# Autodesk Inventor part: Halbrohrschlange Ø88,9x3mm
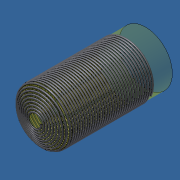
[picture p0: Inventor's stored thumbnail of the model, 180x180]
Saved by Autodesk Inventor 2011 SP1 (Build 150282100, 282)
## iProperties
Created: 2012-07
Part Number: Halbrohrschlange Ø88,9x3mm
Material: 1.4301
Document SubType Name: Modeling
Designer: S. Stark
Mass: 1.1007e+06 g
Surface Area: 958033 cm^2
Volume: 140396 cm^3
Density: 7.84 g/cm^3
Author: S. Stark
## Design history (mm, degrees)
derived "Multibody Halbrohrschlange (2).ipt"
tag "Bezeichnung1"
feature "Volumenkörper6::Multibody Halbrohrschlange (2).ipt" dims "d0" = 10
feature "Volumenkörper7::Multibody Halbrohrschlange (2).ipt" dims "d0" = 10
feature "Flächen1::Multibody Halbrohrschlange (2).ipt"
node "Flächen1"
node "Volumenkörper1"
node "Volumenkörper2"
node "Volumenkörper3"
